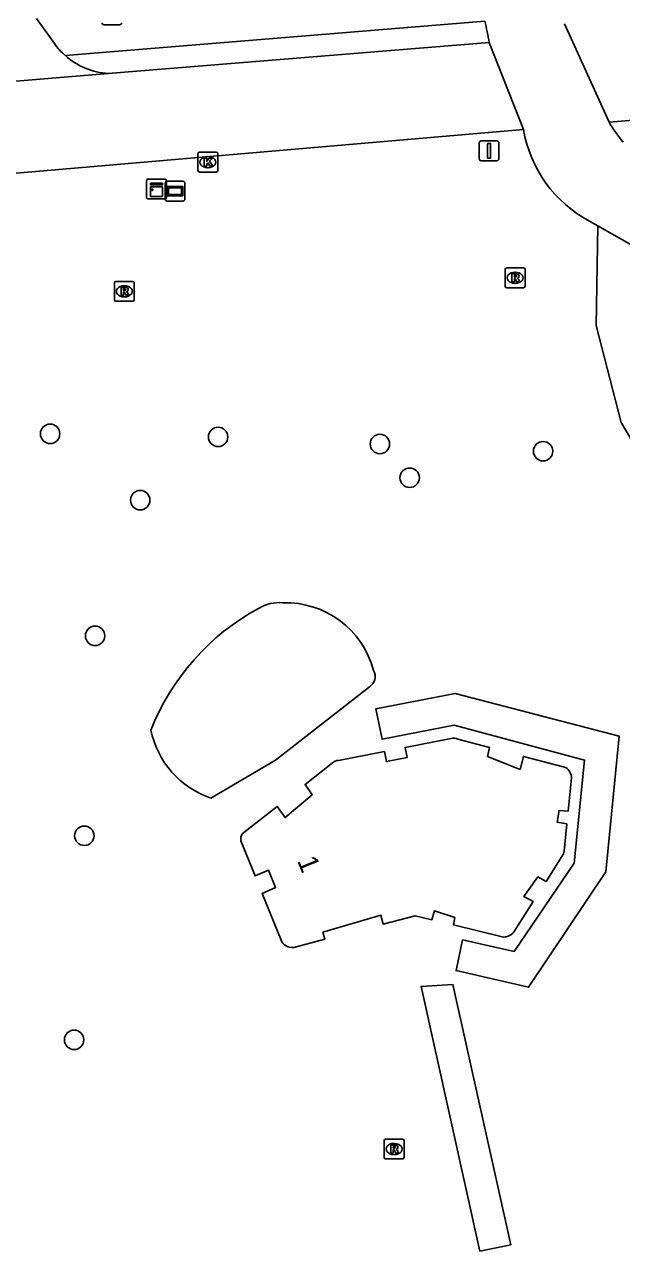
# Model space of a CAD drawing. Extents: x 156664 to 157568, y 383571 to 384421.
# Drawn here: x 157076.5 to 157106.5, y 383875.5 to 383937.7 of the extents above; entities that cross this region are included whole.
import ezdxf

# ---------------------------------------------------------------- set-up
doc = ezdxf.new("R2010")
doc.units = 0
for name, color, linetype in [('IMGEO_Boom', 7, 'Continuous'), ('IMGEO_Fietspad_gesloten', 7, 'Continuous'), ('IMGEO_Kast', 7, 'Continuous'), ('IMGEO_Kolk', 7, 'Continuous'), ('IMGEO_Lichtpunt', 7, 'Continuous'), ('IMGEO_Loofbos', 7, 'Continuous'), ('IMGEO_Meer_plas_ven_vijver', 7, 'Continuous'), ('IMGEO_Pand', 7, 'Continuous'), ('IMGEO_Pand_nummerreeks', 7, 'Continuous'), ('IMGEO_Rijbaan_lokaal_open', 7, 'Continuous'), ('IMGEO_Rioolput', 7, 'Continuous'), ('IMGEO_Verkeersbordpaal', 7, 'Continuous'), ('IMGEO_Verklikker', 7, 'Continuous'), ('IMGEO_Voetpad_open', 7, 'Continuous')]:
    doc.layers.add(name, color=color, linetype=linetype)

msp = doc.modelspace()

# ---------------------------------------------------------------- linework, layer by layer
at = {"layer": 'IMGEO_Boom'}
for centre in [(157077.734, 383917.141), (157086.187, 383916.985), (157094.329, 383916.628), (157102.541, 383916.267), (157095.826, 383914.932), (157082.266, 383913.802), (157079.996, 383906.975), (157079.454, 383896.915), (157078.941, 383886.643)]:
    msp.add_circle(centre, 0.489, dxfattribs=at)
at = {"layer": 'IMGEO_Fietspad_gesloten'}
for points in [[(157104.879, 383927.836), (157105.291, 383927.602)], [(157110.006, 383924.797), (157107.584, 383926.297), (157105.291, 383927.602)]]:
    msp.add_lwpolyline(points, dxfattribs=at)
msp.add_arc((157107.946, 383933.557), 6.491, 189.80671, 241.80239, dxfattribs=at)
at = {"layer": 'IMGEO_Kast'}
for p, q in [((157082.588, 383929.035), (157082.588, 383929.876)), ((157082.588, 383929.876), (157082.588, 383929.035)), ((157082.663, 383929.96), (157083.504, 383929.96)), ((157083.504, 383929.96), (157082.663, 383929.96)), ((157083.588, 383929.885), (157083.588, 383929.044)), ((157083.588, 383929.044), (157083.588, 383929.885)), ((157083.513, 383928.96), (157082.672, 383928.96)), ((157082.672, 383928.96), (157083.513, 383928.96))]:
    msp.add_line(p, q, dxfattribs=at)
for points in [[(157082.783, 383929.75), (157083.383, 383929.75), (157083.383, 383929.665), (157082.783, 383929.665), (157082.783, 383929.75)], [(157082.783, 383929.575), (157083.383, 383929.575), (157083.383, 383929.086), (157082.783, 383929.086), (157082.783, 383929.575)]]:
    msp.add_lwpolyline(points, dxfattribs=at)
msp.add_circle((157082.867, 383929.424), 0.0377, dxfattribs=at)
for centre, start, end in [((157082.666, 383929.882), 92.4484, 184.28452), ((157082.666, 383929.882), 92.4484, 184.28452), ((157083.51, 383929.882), 2.4484, 94.28452), ((157083.51, 383929.882), 2.4484, 94.28452), ((157082.666, 383929.038), 182.4484, 274.28452), ((157082.666, 383929.038), 182.4484, 274.28452), ((157083.51, 383929.038), 272.4484, 4.28452), ((157083.51, 383929.038), 272.4484, 4.28452)]:
    msp.add_arc(centre, 0.0779, start, end, dxfattribs=at)
at = {"layer": 'IMGEO_Kolk'}
for p, q in [((157085.169, 383930.388), (157085.169, 383931.24)), ((157085.244, 383931.314), (157086.096, 383931.314)), ((157085.657, 383931.094), (157085.682, 383931.094)), ((157086.17, 383931.24), (157086.17, 383930.388)), ((157086.096, 383930.314), (157085.244, 383930.314)), ((157085.68, 383930.534), (157085.655, 383930.534))]:
    msp.add_line(p, q, dxfattribs=at)
for points in [[(157085.169, 383930.388), (157085.169, 383931.24)], [(157085.244, 383931.314), (157086.096, 383931.314)], [(157085.49, 383931.014), (157085.613, 383931.014), (157085.613, 383930.863), (157085.743, 383931.014), (157085.907, 383931.014), (157085.761, 383930.863), (157085.914, 383930.614), (157085.762, 383930.614), (157085.677, 383930.778), (157085.613, 383930.711), (157085.613, 383930.614), (157085.49, 383930.614), (157085.49, 383931.014)], [(157086.17, 383931.24), (157086.17, 383930.388)], [(157086.096, 383930.314), (157085.244, 383930.314)]]:
    msp.add_lwpolyline(points, dxfattribs=at)
for centre, start, end in [((157085.246, 383931.238), 91.55205, 178.44795), ((157085.246, 383931.238), 91.55205, 178.44795), ((157086.094, 383931.238), 1.55205, 88.44795), ((157086.094, 383931.238), 1.55205, 88.44795), ((157085.246, 383930.39), 181.55205, 268.44795), ((157085.246, 383930.39), 181.55205, 268.44795), ((157086.094, 383930.39), 271.55205, 358.44795), ((157086.094, 383930.39), 271.55205, 358.44795)]:
    msp.add_arc(centre, 0.0765, start, end, dxfattribs=at)
for centre, major_axis, ratio, start_param, end_param in [((157085.656, 383930.814), (-0.387, 0.002), 0.722429, 4.712389, 7.853982), ((157085.681, 383930.814), (-0.39, 0.002), 0.717154, 1.570796, 4.712389)]:
    msp.add_ellipse(centre, major_axis=major_axis, ratio=ratio, start_param=start_param, end_param=end_param, dxfattribs=at)
at = {"layer": 'IMGEO_Lichtpunt'}
msp.add_line((157080.438, 383937.731), (157081.246, 383937.731), dxfattribs=at)
msp.add_line((157080.438, 383937.731), (157081.246, 383937.731), dxfattribs=at)
for centre, start, end in [((157080.438, 383937.825), 180, 270), ((157080.438, 383937.825), 180, 270), ((157081.246, 383937.825), 270, 0), ((157081.246, 383937.825), 270, 360)]:
    msp.add_arc(centre, 0.0946, start, end, dxfattribs=at)
at = {"layer": 'IMGEO_Loofbos'}
msp.add_lwpolyline([(157105.291, 383927.602), (157105.217, 383922.59), (157106.471, 383917.709), (157108.582, 383914.146), (157111.616, 383909.66), (157115.706, 383903.591), (157118.477, 383892.64), (157127.449, 383856.225), (157134.31, 383847.517), (157134.838, 383843.163), (157131.671, 383843.163), (157127.449, 383844.35), (157110.825, 383843.295), (157107.856, 383840.062), (157101.325, 383837.028), (157095.948, 383836.137), (157091.43, 383836.764), (157087.933, 383839.93), (157084.173, 383842.503), (157076.52, 383846.989), (157071.375, 383853.718), (157065.965, 383853.982), (157057.767, 383858.53)], dxfattribs=at)
at = {"layer": 'IMGEO_Meer_plas_ven_vijver'}
msp.add_lwpolyline([(157085.827, 383898.81), (157089.067, 383900.723), (157093.802, 383904.415)], dxfattribs=at)
for centre, radius, start, end in [((157093.955, 383897.825), 11.992, 118.55816, 158.42266), ((157089.244, 383906.683), 1.962, 84.1754, 121.38851), ((157089.605, 383904.095), 4.543, 14.50344, 92.04681), ((157093.494, 383904.924), 0.596, 301.19119, 31.19825), ((157087.301, 383903.159), 4.592, 191.60689, 251.27695)]:
    msp.add_arc(centre, radius, start, end, dxfattribs=at)
at = {"layer": 'IMGEO_Pand'}
for points in [[(157097.911, 383901.809), (157095.606, 383901.356), (157095.706, 383900.855), (157094.659, 383900.649), (157094.559, 383901.149), (157092.243, 383900.694)], [(157103.684, 383900.345), (157101.551, 383900.907), (157101.378, 383900.251), (157099.744, 383900.906), (157099.837, 383901.358), (157098.243, 383901.778)], [(157091.943, 383900.577), (157090.565, 383899.495), (157090.924, 383898.973), (157089.56, 383897.825), (157089.162, 383898.393), (157087.401, 383897.01)], [(157103.738, 383897.511), (157103.244, 383897.598), (157103.348, 383898.189), (157103.804, 383898.156), (157103.975, 383899.827)], [(157101.085, 383892.091), (157102.044, 383893.598), (157101.571, 383893.855), (157102.283, 383894.844), (157102.692, 383894.616), (157103.571, 383895.998), (157103.597, 383896.138), (157103.738, 383897.511)], [(157087.337, 383896.654), (157088.05, 383894.89), (157088.727, 383895.19), (157089.08, 383894.312), (157088.405, 383894.014), (157089.354, 383891.665)], [(157089.991, 383891.295), (157091.56, 383891.704), (157091.462, 383892.068), (157094.374, 383892.915), (157094.499, 383892.469), (157096.106, 383892.888), (157096.939, 383892.687), (157097.069, 383893.129), (157098.098, 383892.802), (157098.023, 383892.424), (157100.546, 383891.814)]]:
    msp.add_lwpolyline(points, dxfattribs=at)
for centre, radius, start, end in [((157098.033, 383901.317), 0.507, 65.45508, 103.87604), ((157092.209, 383900.338), 0.358, 84.54878, 138.06278), ((157103.31, 383899.794), 0.665, 2.81316, 55.8393), ((157087.744, 383896.765), 0.421, 144.39651, 195.22048), ((157089.9, 383891.872), 0.584, 200.78141, 278.91847), ((157100.543, 383892.482), 0.668, 270.22256, 324.17604)]:
    msp.add_arc(centre, radius, start, end, dxfattribs=at)
at = {"layer": 'IMGEO_Rijbaan_lokaal_open'}
for points in [[(157077.95, 383936.786), (157077.04, 383938.041)], [(157078.499, 383936.173), (157099.608, 383937.911)], [(157105.861, 383932.834), (157103.623, 383937.774)], [(157099.825, 383936.843), (157080.659, 383935.273)], [(157101.55, 383932.451), (157099.825, 383936.843)], [(157080.659, 383935.273), (157071.766, 383934.544), (157069.139, 383934.324)], [(157110.054, 383933.183), (157105.861, 383932.834)], [(157075.258, 383930.194), (157101.55, 383932.451)]]:
    msp.add_lwpolyline(points, dxfattribs=at)
for centre, radius, start, end in [((157086.109, 383934.612), 13.896, 9.23788, 13.73254), ((157080.913, 383938.887), 3.633, 215.34385, 228.35111), ((157080.891, 383938.871), 3.605, 228.44398, 266.31629), ((157111.24, 383935.877), 6.18, 209.49331, 221.0129)]:
    msp.add_arc(centre, radius, start, end, dxfattribs=at)
at = {"layer": 'IMGEO_Rioolput'}
for p, q in [((157100.633, 383924.569), (157100.633, 383925.421)), ((157100.708, 383925.495), (157101.56, 383925.495)), ((157101.121, 383925.275), (157101.146, 383925.275)), ((157101.634, 383925.421), (157101.634, 383924.569)), ((157080.965, 383923.886), (157080.965, 383924.738)), ((157081.04, 383924.812), (157081.892, 383924.812)), ((157081.453, 383924.592), (157081.478, 383924.592)), ((157081.966, 383924.738), (157081.966, 383923.886)), ((157101.56, 383924.495), (157100.708, 383924.495)), ((157101.144, 383924.715), (157101.119, 383924.715)), ((157081.476, 383924.032), (157081.451, 383924.032)), ((157081.892, 383923.812), (157081.04, 383923.812)), ((157094.616, 383881.647), (157095.468, 383881.647)), ((157094.541, 383880.721), (157094.541, 383881.573)), ((157095.029, 383881.427), (157095.054, 383881.427)), ((157095.542, 383881.573), (157095.542, 383880.721)), ((157095.468, 383880.647), (157094.616, 383880.647)), ((157095.052, 383880.867), (157095.027, 383880.867))]:
    msp.add_line(p, q, dxfattribs=at)
for points in [[(157100.633, 383924.569), (157100.633, 383925.421)], [(157100.708, 383925.495), (157101.56, 383925.495)], [(157101.222, 383925.193), (157100.97, 383925.195), (157100.97, 383924.795)], [(157101.148, 383925.114), (157101.094, 383925.114), (157101.094, 383925.033)], [(157101.634, 383925.421), (157101.634, 383924.569)], [(157080.965, 383923.886), (157080.965, 383924.738)], [(157081.04, 383924.812), (157081.892, 383924.812)], [(157081.554, 383924.51), (157081.302, 383924.512), (157081.302, 383924.112)], [(157081.966, 383924.738), (157081.966, 383923.886)], [(157101.56, 383924.495), (157100.708, 383924.495)], [(157100.97, 383924.795), (157101.094, 383924.795), (157101.094, 383924.957), (157101.105, 383924.957)], [(157101.094, 383925.033), (157101.146, 383925.033)], [(157101.152, 383924.928), (157101.223, 383924.795), (157101.363, 383924.795), (157101.298, 383924.921)], [(157081.302, 383924.112), (157081.426, 383924.112), (157081.426, 383924.274), (157081.437, 383924.274)], [(157081.48, 383924.431), (157081.426, 383924.431), (157081.426, 383924.35)], [(157081.426, 383924.35), (157081.478, 383924.35)], [(157081.484, 383924.245), (157081.555, 383924.112), (157081.695, 383924.112), (157081.63, 383924.238)], [(157081.892, 383923.812), (157081.04, 383923.812)], [(157094.616, 383881.647), (157095.468, 383881.647)], [(157094.541, 383880.721), (157094.541, 383881.573)], [(157095.13, 383881.345), (157094.878, 383881.347), (157094.878, 383880.947)], [(157094.878, 383880.947), (157095.002, 383880.947), (157095.002, 383881.109), (157095.013, 383881.109)], [(157095.056, 383881.266), (157095.002, 383881.266), (157095.002, 383881.185)], [(157095.002, 383881.185), (157095.054, 383881.185)], [(157095.06, 383881.08), (157095.131, 383880.947), (157095.271, 383880.947), (157095.206, 383881.073)], [(157095.542, 383881.573), (157095.542, 383880.721)], [(157095.468, 383880.647), (157094.616, 383880.647)]]:
    msp.add_lwpolyline(points, dxfattribs=at)
for centre, radius, start, end in [((157100.71, 383925.419), 0.0765, 91.55205, 178.44795), ((157100.71, 383925.419), 0.0765, 91.55205, 178.44795), ((157101.154, 383925.018), 0.0964, 77.00612, 93.18647), ((157101.168, 383925.075), 0.0378, 276.66336, 79.67722), ((157101.221, 383925.083), 0.109, 350.36119, 89.41601), ((157101.558, 383925.419), 0.0765, 1.55205, 88.44795), ((157101.558, 383925.419), 0.0765, 1.55205, 88.44795), ((157081.042, 383924.736), 0.0765, 91.55205, 178.44795), ((157081.042, 383924.736), 0.0765, 91.55205, 178.44795), ((157081.553, 383924.4), 0.109, 350.36119, 89.41601), ((157081.89, 383924.736), 0.0765, 1.55205, 88.44795), ((157081.89, 383924.736), 0.0765, 1.55205, 88.44795), ((157100.71, 383924.571), 0.0765, 181.55205, 268.44795), ((157100.71, 383924.571), 0.0765, 181.55205, 268.44795), ((157101.104, 383924.904), 0.0533, 26.02933, 88.69889), ((157101.13, 383925.222), 0.19, 274.7715, 282.96867), ((157101.219, 383925.083), 0.112, 277.58423, 350.98172), ((157101.203, 383924.868), 0.108, 29.51342, 73.79051), ((157101.558, 383924.571), 0.0765, 271.55205, 358.44795), ((157101.558, 383924.571), 0.0765, 271.55205, 358.44795), ((157081.042, 383923.888), 0.0765, 181.55205, 268.44795), ((157081.042, 383923.888), 0.0765, 181.55205, 268.44795), ((157081.436, 383924.221), 0.0533, 26.02933, 88.69889), ((157081.462, 383924.539), 0.19, 274.7715, 282.96867), ((157081.486, 383924.335), 0.0964, 77.00612, 93.18647), ((157081.5, 383924.392), 0.0378, 276.66336, 79.67722), ((157081.551, 383924.4), 0.112, 277.58423, 350.98172), ((157081.535, 383924.185), 0.108, 29.51342, 73.79051), ((157081.89, 383923.888), 0.0765, 271.55205, 358.44795), ((157081.89, 383923.888), 0.0765, 271.55205, 358.44795), ((157094.618, 383881.571), 0.0765, 91.55205, 178.44795), ((157094.618, 383881.571), 0.0765, 91.55205, 178.44795), ((157095.466, 383881.571), 0.0765, 1.55205, 88.44795), ((157095.466, 383881.571), 0.0765, 1.55205, 88.44795), ((157095.012, 383881.056), 0.0533, 26.02933, 88.69889), ((157095.038, 383881.374), 0.19, 274.7715, 282.96867), ((157095.062, 383881.17), 0.0964, 77.00612, 93.18647), ((157095.076, 383881.227), 0.0378, 276.66336, 79.67722), ((157095.129, 383881.235), 0.109, 350.36119, 89.41601), ((157095.127, 383881.235), 0.112, 277.58423, 350.98172), ((157095.111, 383881.02), 0.108, 29.51342, 73.79051), ((157094.618, 383880.723), 0.0765, 181.55205, 268.44795), ((157094.618, 383880.723), 0.0765, 181.55205, 268.44795), ((157095.466, 383880.723), 0.0765, 271.55205, 358.44795), ((157095.466, 383880.723), 0.0765, 271.55205, 358.44795)]:
    msp.add_arc(centre, radius, start, end, dxfattribs=at)
for centre, major_axis, ratio, start_param, end_param in [((157101.12, 383924.995), (-0.387, 0.002), 0.722429, 4.712389, 7.853982), ((157101.145, 383924.995), (-0.39, 0.002), 0.717154, 1.570796, 4.712389), ((157081.452, 383924.312), (-0.387, 0.002), 0.722429, 4.712389, 7.853982), ((157081.477, 383924.312), (-0.39, 0.002), 0.717154, 1.570796, 4.712389), ((157095.028, 383881.147), (-0.387, 0.002), 0.722429, 4.712389, 7.853982), ((157095.053, 383881.147), (-0.39, 0.002), 0.717154, 1.570796, 4.712389)]:
    msp.add_ellipse(centre, major_axis=major_axis, ratio=ratio, start_param=start_param, end_param=end_param, dxfattribs=at)
at = {"layer": 'IMGEO_Verkeersbordpaal'}
for p, q in [((157099.325, 383930.981), (157099.325, 383931.781)), ((157099.325, 383931.781), (157099.325, 383930.981)), ((157099.425, 383931.881), (157100.215, 383931.881)), ((157100.215, 383931.881), (157099.425, 383931.881)), ((157100.315, 383931.781), (157100.315, 383930.981)), ((157100.315, 383930.981), (157100.315, 383931.781)), ((157100.215, 383930.881), (157099.425, 383930.881)), ((157099.425, 383930.881), (157100.215, 383930.881))]:
    msp.add_line(p, q, dxfattribs=at)
msp.add_lwpolyline([(157099.745, 383931.756), (157099.895, 383931.756), (157099.895, 383931.006), (157099.745, 383931.006), (157099.745, 383931.756)], dxfattribs=at)
for centre, start, end in [((157099.425, 383931.781), 90, 180), ((157099.425, 383931.781), 90, 180), ((157100.215, 383931.781), 0, 90), ((157100.215, 383931.781), 360, 90), ((157099.425, 383930.981), 180, 270), ((157099.425, 383930.981), 180, 270), ((157100.215, 383930.981), 270, 0), ((157100.215, 383930.981), 270, 0)]:
    msp.add_arc(centre, 0.1, start, end, dxfattribs=at)
at = {"layer": 'IMGEO_Verklikker'}
for p, q in [((157083.525, 383928.956), (157083.525, 383929.756)), ((157083.525, 383929.756), (157083.525, 383928.956)), ((157083.625, 383929.856), (157084.415, 383929.856)), ((157084.415, 383929.856), (157083.625, 383929.856)), ((157084.515, 383929.756), (157084.515, 383928.956)), ((157084.515, 383928.956), (157084.515, 383929.756)), ((157084.415, 383928.856), (157083.625, 383928.856)), ((157083.625, 383928.856), (157084.415, 383928.856))]:
    msp.add_line(p, q, dxfattribs=at)
for points in [[(157083.626, 383929.588), (157084.414, 383929.588), (157084.414, 383929.124), (157083.626, 383929.124), (157083.626, 383929.588)], [(157083.691, 383929.523), (157083.691, 383929.189), (157084.349, 383929.189), (157084.349, 383929.523), (157083.691, 383929.523)]]:
    msp.add_lwpolyline(points, dxfattribs=at)
for centre, start, end in [((157083.625, 383929.756), 90, 180), ((157083.625, 383929.756), 90, 180), ((157084.415, 383929.756), 0, 90), ((157084.415, 383929.756), 360, 90), ((157083.625, 383928.956), 180, 270), ((157083.625, 383928.956), 180, 270), ((157084.415, 383928.956), 270, 0), ((157084.415, 383928.956), 270, 0)]:
    msp.add_arc(centre, 0.1, start, end, dxfattribs=at)
at = {"layer": 'IMGEO_Voetpad_open'}
for points in [[(157098.482, 383891.682), (157098.163, 383890.125), (157101.806, 383889.293), (157105.701, 383895.095), (157106.372, 383901.925), (157098.118, 383904.073), (157094.126, 383903.308), (157094.438, 383901.77), (157098.063, 383902.478), (157104.625, 383900.726), (157104.103, 383895.538), (157101.087, 383891.095), (157098.482, 383891.682)], [(157099.351, 383876.008), (157100.914, 383876.329), (157097.999, 383889.422), (157096.401, 383889.329), (157099.351, 383876.008)]]:
    msp.add_lwpolyline(points, dxfattribs=at)

# ---------------------------------------------------------------- texts
at = {"layer": 'IMGEO_Pand_nummerreeks'}
msp.add_text('1', height=1, rotation=291.90397, dxfattribs=at).set_placement((157090.155, 383895.66))

doc.saveas('drawing.dxf')
